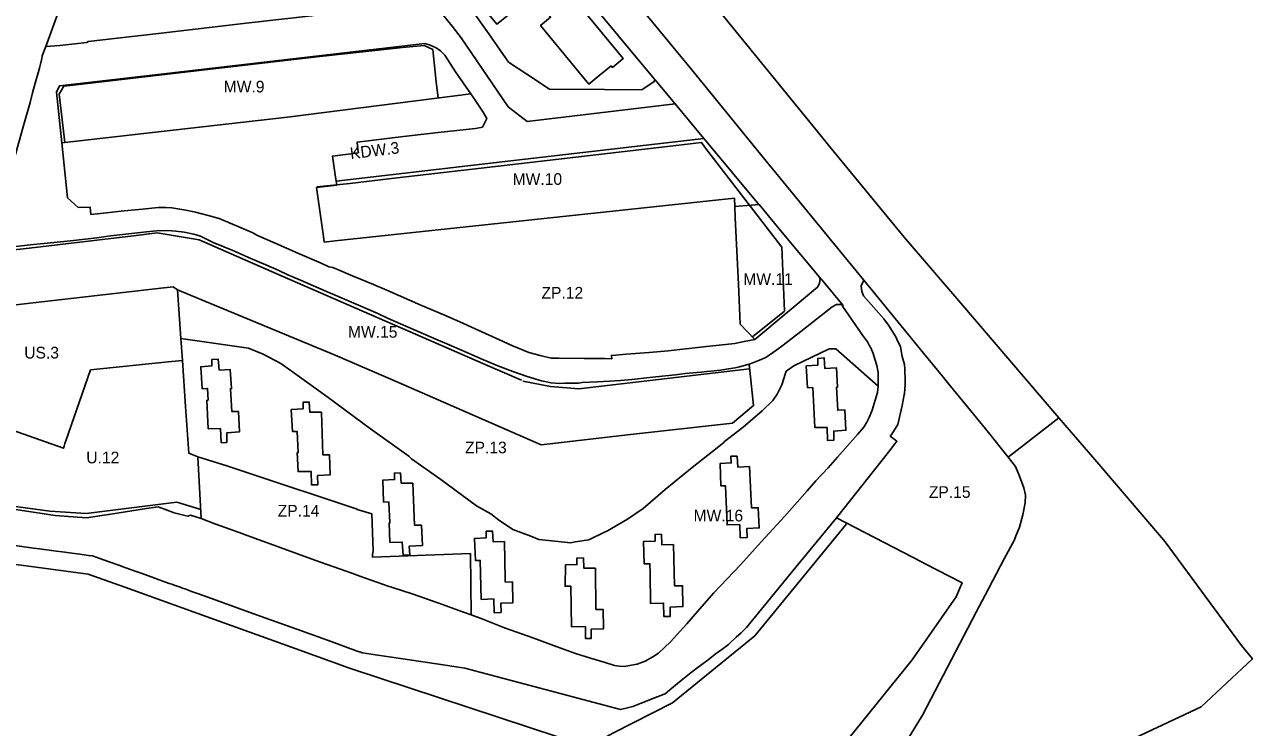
# Model space of a CAD drawing. Extents: x 7428689 to 7430424, y 5549101 to 5550539.
# Drawn here: x 7429899 to 7430424, y 5549654 to 5549955 of the extents above; entities that cross this region are included whole.
import ezdxf

# ---------------------------------------------------------------- set-up
doc = ezdxf.new("R2010")
doc.units = 0
for name, color, linetype in [('linie rozgraniczające', 7, 'Continuous'), ('nieprzekraczalne linie zabudowy', 7, 'Continuous'), ('obowiazujace linie zabudowy', 7, 'Continuous'), ('przeznaczenia terenów', 7, 'Continuous')]:
    doc.layers.add(name, color=color, linetype=linetype)

msp = doc.modelspace()

# ---------------------------------------------------------------- linework, layer by layer
at = {"layer": 'linie rozgraniczające'}
for points in [[(7429816.83, 5550334.12), (7429833.34, 5550323.51), (7429855.56, 5550306.27), (7429881.93, 5550290.04), (7429926.89, 5550263.18), (7429964.68, 5550236.86), (7430011.43, 5550186.87), (7430059.81, 5550126.71), (7430101.57, 5550076.38), (7430124.52, 5550048.84), (7430239.35, 5549907.74), (7430243.53, 5549902.67), (7430275.28, 5549864.05), (7430299.52, 5549835.73), (7430341.5, 5549786.7)], [(7430258.04, 5549845.58), (7430248.2, 5549857.63), (7430222.19, 5549889.25), (7430215.68, 5549897.16), (7430184.53, 5549935.61), (7430156.23, 5549969.99), (7430153.13, 5549973.76), (7430122.35, 5550011.53), (7430090.9, 5550049.78), (7430068.9, 5550076.43)], [(7430096.23, 5550017.94), (7430104.53, 5550007.9), (7430112.53, 5549999.04), (7430137.26, 5549969.22), (7430168.39, 5549931.68), (7430168.64, 5549931.38)], [(7430168.64, 5549931.38), (7430168.37, 5549930.61), (7430163.03, 5549927.09), (7430147.1, 5549927.18), (7430123.56, 5549927.32), (7430113.91, 5549933.66), (7430105.97, 5549938.87), (7430097.56, 5549950.93), (7430089.55, 5549962.42), (7430083.75, 5549970.74), (7430074.73, 5549983.7), (7430067.39, 5549994.23)], [(7429908.04, 5549945.59), (7429916.81, 5549969.68)], [(7430085.82, 5549949.33), (7430081.94, 5549954.22), (7430076.43, 5549961.08), (7430066.36, 5549963.92), (7430053.83, 5549962.51), (7430036.17, 5549960.52), (7430026.92, 5549959.51), (7430021.76, 5549958.62), (7429993.81, 5549955.51), (7429956.35, 5549951.19), (7429926.16, 5549947.7), (7429925.68, 5549947.31), (7429914.12, 5549946.03), (7429908.04, 5549945.59)], [(7429914.96, 5549904.32), (7429912.68, 5549925.96), (7429913.89, 5549928.71), (7429960.94, 5549934.15), (7430070.26, 5549946.8), (7430072.5, 5549946.14), (7430075.15, 5549944.97), (7430077, 5549943.65), (7430078.75, 5549941.8), (7430083.3, 5549934.76), (7430089.91, 5549925.26)], [(7430177.27, 5549921.04), (7430114.02, 5549913.44), (7430105.92, 5549919.76), (7430085.82, 5549949.33)], [(7429908.04, 5549945.59), (7429906.58, 5549941.5), (7429906.31, 5549940.37), (7429905.33, 5549936.24), (7429903.54, 5549929.81), (7429902.43, 5549925.68), (7429901.44, 5549921.63), (7429898.46, 5549911.23), (7429894.97, 5549898.89), (7429891.24, 5549885.87), (7429889.75, 5549880.65), (7429893.15, 5549880.55), (7429892.34, 5549877.29), (7429887.85, 5549859.16)], [(7430177.27, 5549921.04), (7430168.64, 5549931.38)], [(7430089.91, 5549925.26), (7430011.45, 5549915.27), (7429956.31, 5549909.01), (7429914.96, 5549904.32)], [(7430089.91, 5549925.26), (7430091.18, 5549923.44), (7430095.26, 5549917.51), (7430096.74, 5549914.71), (7430094.9, 5549911.04), (7430091.98, 5549910.54), (7430075.97, 5549908.75), (7430061.15, 5549907.03), (7430041.31, 5549904.65), (7430041.59, 5549901.54), (7430041.8, 5549900.07), (7430030.69, 5549898.67), (7430031.86, 5549890.61), (7430032.24, 5549887.95)], [(7430189.61, 5549906.24), (7430177.27, 5549921.04)], [(7430211.47, 5549820.24), (7430206.91, 5549819.33), (7430202.91, 5549818.53), (7430189.5, 5549817.02), (7430174.34, 5549815.35), (7430166.24, 5549814.68), (7430156.4, 5549813.89), (7430151.99, 5549813.53), (7430150.09, 5549813.41), (7430150.19, 5549811.98), (7430147.22, 5549812.01), (7430138.41, 5549812.09), (7430127.51, 5549812.27), (7430124.34, 5549812.27), (7430119.58, 5549813.34), (7430114.77, 5549814.61), (7430107.43, 5549817.59), (7430102.19, 5549820.05), (7430099.06, 5549821.48), (7430091.71, 5549824.81), (7430085.17, 5549827.71), (7430078.38, 5549830.69), (7430068.58, 5549834.93), (7430053.93, 5549841.36), (7430048.22, 5549843.67), (7430039.64, 5549847.28), (7430033.57, 5549849.86), (7430030.91, 5549850.97), (7430029.17, 5549851.33), (7430025.95, 5549852.87), (7430015.91, 5549857.2), (7430006.19, 5549861.45), (7429998.69, 5549864.66), (7429996.39, 5549866.03), (7429982.26, 5549872), (7429978.17, 5549873.11), (7429972.18, 5549874.66), (7429967.93, 5549875.57), (7429961.94, 5549876.49), (7429959.48, 5549876.73), (7429956.1, 5549876.69), (7429949.4, 5549875.97), (7429941.66, 5549875.3), (7429934, 5549874.38), (7429927.33, 5549873.75), (7429926.99, 5549876.86), (7429921.98, 5549876.65), (7429917.42, 5549880.87), (7429914.96, 5549904.32)], [(7430032.24, 5549887.95), (7430099.64, 5549895.78), (7430189.61, 5549906.24)], [(7430213.22, 5549877.92), (7430213.14, 5549878.02), (7430190.61, 5549905.04), (7430189.61, 5549906.24)], [(7430202.85, 5549877.11), (7430202.7, 5549880.65), (7430031.88, 5549862.4), (7430027.23, 5549861.91), (7430026.72, 5549865.46), (7430026.71, 5549865.47), (7430026.46, 5549867.28), (7430023.96, 5549885.17), (7430032.53, 5549886.26), (7430032.24, 5549887.95)], [(7430213.22, 5549877.92), (7430202.85, 5549877.11)], [(7430239.09, 5549846.91), (7430223.13, 5549866.05), (7430213.22, 5549877.92)], [(7430211.47, 5549820.24), (7430205.17, 5549826.7), (7430204.38, 5549843.82), (7430203.07, 5549872.23), (7430202.85, 5549877.11)], [(7429887.85, 5549859.16), (7429901.45, 5549860.72), (7429911.55, 5549861.69), (7429918.71, 5549862.38), (7429929.84, 5549863.74), (7429935.75, 5549864.53), (7429943.45, 5549865.41), (7429951.15, 5549866.2), (7429955.39, 5549866.68), (7429960.28, 5549866.87), (7429963.77, 5549866.59), (7429967.27, 5549866.07), (7429971.35, 5549865.2), (7429974.28, 5549864.35), (7429979.75, 5549861.75), (7429988.81, 5549857.94), (7429994.74, 5549855.28), (7430002.21, 5549852.08), (7430007.73, 5549849.69), (7430011.59, 5549847.91), (7430017.07, 5549845.63), (7430022.59, 5549843.17), (7430027.23, 5549841.2), (7430031.84, 5549839.21), (7430037.9, 5549836.59), (7430044.82, 5549833.6), (7430050.07, 5549831.3), (7430054.28, 5549829.35), (7430059.82, 5549826.94), (7430066.41, 5549824.04), (7430073.99, 5549820.8), (7430081.58, 5549817.5), (7430088.21, 5549814.6), (7430095.32, 5549811.53), (7430101.5, 5549808.99), (7430107.85, 5549806.51), (7430114.01, 5549804.35), (7430120.22, 5549802.55), (7430124.23, 5549801.61), (7430127.88, 5549801.42), (7430130.13, 5549801.52), (7430135.95, 5549801.57), (7430137.56, 5549801.78), (7430143.97, 5549802.1), (7430149.26, 5549802.33), (7430153.9, 5549802.69), (7430158.79, 5549803.13), (7430166.41, 5549803.89), (7430173.16, 5549804.68), (7430177.52, 5549805.14), (7430181.61, 5549805.63), (7430188.42, 5549806.26), (7430190.87, 5549806.49), (7430192.63, 5549806.65), (7430196.76, 5549807.15), (7430200.21, 5549807.58), (7430203.03, 5549808.09), (7430204.93, 5549808.47), (7430208.47, 5549809.5), (7430208.97, 5549809.68)], [(7430239.09, 5549846.91), (7430239.33, 5549845.93), (7430239.25, 5549845.1), (7430239.08, 5549844.32), (7430238.42, 5549842.71), (7430238.26, 5549842.57), (7430211.47, 5549820.24)], [(7430249.2, 5549834.78), (7430240.88, 5549844.76), (7430239.09, 5549846.91)], [(7429881.49, 5549833.5), (7429958.54, 5549842.32), (7429958.76, 5549842.35), (7429962.6, 5549842.78), (7429964.4, 5549841.52)], [(7429964.4, 5549841.52), (7429965.85, 5549820.63)], [(7430208.97, 5549809.68), (7430210.81, 5549791.9), (7430201.89, 5549784.46), (7430158.16, 5549779.51), (7430119.94, 5549775.19), (7430058.9, 5549801.77), (7430031.87, 5549813.54), (7429964.4, 5549841.52)], [(7430258.04, 5549845.58), (7430256.98, 5549843.23), (7430257.18, 5549840.73), (7430257.94, 5549838.91), (7430266.64, 5549829.1), (7430268.58, 5549826.4), (7430271.78, 5549821.3), (7430272.2, 5549820.36), (7430273.68, 5549817.02), (7430274.48, 5549812.98), (7430275.46, 5549809.46), (7430275.56, 5549807.49), (7430275.64, 5549805.71), (7430275.69, 5549804.29), (7430275.8, 5549801.16), (7430275.46, 5549796.89), (7430275.38, 5549796.54), (7430274.39, 5549791.9), (7430272.56, 5549783.86), (7430270.02, 5549779.69), (7430269.38, 5549778.88), (7430272.21, 5549776.64), (7430271.37, 5549775.51), (7430268.54, 5549771.99), (7430246.32, 5549743.93)], [(7430319.78, 5549769.81), (7430311.41, 5549780.44), (7430302.38, 5549791.45), (7430294.46, 5549801.11), (7430291.51, 5549804.71), (7430283.63, 5549814.32), (7430279.79, 5549819), (7430276.63, 5549822.86), (7430258.04, 5549845.58)], [(7430208.97, 5549809.68), (7430210.63, 5549810.27), (7430213.37, 5549811.3), (7430213.38, 5549811.3), (7430216.11, 5549812.55), (7430220.77, 5549815.83), (7430223.52, 5549817.74), (7430231.09, 5549823.61), (7430241.78, 5549831.97), (7430244.53, 5549834.14), (7430246.38, 5549835.2), (7430248.41, 5549835.14), (7430249.2, 5549834.78)], [(7430264.21, 5549800.27), (7430264.24, 5549800.51), (7430264.24, 5549804.01), (7430264.2, 5549806.07), (7430263.57, 5549809.01), (7430262.82, 5549811.82), (7430262.02, 5549814.28), (7430260.99, 5549816.63), (7430260.31, 5549817.78), (7430259.56, 5549819.17), (7430257.5, 5549822.1), (7430254.36, 5549826.67), (7430248.89, 5549834.52), (7430249.2, 5549834.78)], [(7429966.5, 5549811.25), (7429965.85, 5549820.63)], [(7429965.85, 5549820.63), (7429994.82, 5549816.43), (7430001.1, 5549813.98), (7430008.63, 5549809.93), (7430013.09, 5549806.85), (7430028.37, 5549795.77), (7430046.99, 5549781.94), (7430063.35, 5549770.24), (7430064.48, 5549769.19), (7430077.06, 5549760.25), (7430092.39, 5549749.02), (7430098.43, 5549745.65), (7430101.78, 5549743.1), (7430107.95, 5549738.97), (7430115.55, 5549736.02), (7430118.96, 5549734.65), (7430132.66, 5549733.27), (7430134.56, 5549733.6), (7430140.46, 5549734.45), (7430147.09, 5549737.73), (7430148.39, 5549738.4), (7430148.45, 5549738.38), (7430156.95, 5549743.31), (7430163.6, 5549747.86), (7430173.04, 5549755.99), (7430184.58, 5549765.43), (7430197.96, 5549776.06), (7430198.48, 5549776.57), (7430206.42, 5549782.66), (7430214.61, 5549789.67), (7430219.07, 5549794.13), (7430220.91, 5549796.82), (7430223, 5549800.82), (7430224.58, 5549805.8), (7430224.84, 5549806.65), (7430228.12, 5549808.95), (7430243.26, 5549816.22), (7430246.02, 5549816.22), (7430264.21, 5549800.27)], [(7429871.39, 5549789.01), (7429888.46, 5549783.29), (7429915.65, 5549773.69), (7429915.92, 5549774.62), (7429916.18, 5549775.67), (7429916.58, 5549776.86), (7429927.23, 5549807.18), (7429960.39, 5549810.65), (7429966.5, 5549811.25)], [(7429973.11, 5549770.05), (7429969.26, 5549771.62), (7429967.87, 5549791.56), (7429966.5, 5549811.25)], [(7430264.21, 5549800.27), (7430263.85, 5549797.5), (7430262.93, 5549794.28), (7430261.58, 5549789.92), (7430260.31, 5549786.82), (7430259.36, 5549784.88), (7430258.09, 5549782.73), (7430255.31, 5549779.52), (7430251.07, 5549774.76), (7430246.74, 5549769.87), (7430242.77, 5549765.35), (7430237.52, 5549759.67), (7430233.8, 5549755.49), (7430224.17, 5549744.54), (7430214.33, 5549733.8), (7430205.33, 5549723.8), (7430193.95, 5549711.76), (7430187.77, 5549704.81), (7430182.27, 5549698.62), (7430175.29, 5549690.84), (7430170.21, 5549686.03), (7430167.72, 5549684.49), (7430164.49, 5549682.64), (7430161.1, 5549681.26), (7430157.03, 5549680.55), (7430155.71, 5549680.36), (7430153.32, 5549680.42), (7430151.37, 5549680.73), (7430147.35, 5549681.95), (7430141.05, 5549683.8), (7430134.7, 5549685.81), (7430126.87, 5549688.67), (7430116.44, 5549692.54), (7430104.35, 5549696.84), (7430095.06, 5549700.48), (7430090.02, 5549702.34)], [(7430341.5, 5549786.7), (7430319.78, 5549769.81)], [(7430341.5, 5549786.7), (7430357.67, 5549767.81), (7430385.38, 5549735.44), (7430386.97, 5549733.58), (7430419.63, 5549689.34), (7430424.31, 5549683.55), (7430402.43, 5549663.1), (7430345.97, 5549636.49)], [(7429973.11, 5549770.05), (7429974.57, 5549743.68)], [(7430090.02, 5549702.34), (7430089.78, 5549728.62), (7430047.91, 5549727.05), (7430047.82, 5549727.57), (7430047.91, 5549728.19), (7430048.08, 5549729.76), (7430047.56, 5549745.67), (7430041.34, 5549747.48), (7430041.33, 5549747.63), (7429994.1, 5549763.35), (7429985.59, 5549766.18), (7429973.11, 5549770.05)], [(7430228.77, 5549605.53), (7430233.54, 5549609.48), (7430238.8, 5549613.84), (7430249.41, 5549622.63), (7430262.18, 5549633.21), (7430267.94, 5549638.53), (7430271.74, 5549642.65), (7430274.9, 5549646.31), (7430278.07, 5549651.09), (7430283.22, 5549659.41), (7430306.17, 5549703.55), (7430310.02, 5549710.88), (7430318.16, 5549726.37), (7430322.45, 5549734.55), (7430322.97, 5549735.78), (7430324.7, 5549739.87), (7430326.07, 5549745.24), (7430327.07, 5549750.27), (7430327.17, 5549753.54), (7430326.55, 5549756.79), (7430324.71, 5549761.7), (7430322.93, 5549765.87), (7430319.78, 5549769.81)], [(7429974.57, 5549743.68), (7429969.96, 5549745.05), (7429968.9, 5549744.66), (7429967.51, 5549744.92), (7429963.01, 5549746.11), (7429960.03, 5549747.24), (7429956.2, 5549748.63), (7429951.17, 5549747.9), (7429935.89, 5549745.52), (7429925.52, 5549743.92), (7429912.08, 5549744.96), (7429871.59, 5549750.98), (7429863.62, 5549752.17)], [(7429894.89, 5549732.03), (7429902.84, 5549730.96), (7429905.36, 5549730.62), (7429911.49, 5549729.81), (7429916.16, 5549729.18), (7429919.26, 5549728.77), (7429922.67, 5549728.31), (7429926.32, 5549727.82), (7429928.12, 5549727.58), (7429931.23, 5549726.47), (7429935.12, 5549725.08), (7429939.3, 5549723.59), (7429941.93, 5549722.64), (7429944.7, 5549721.66), (7429946.29, 5549721.09), (7429948.81, 5549720.19), (7429951.63, 5549719.18), (7429953.52, 5549718.5), (7429956.52, 5549717.43), (7429958.12, 5549716.86), (7429960.9, 5549715.87), (7429962.01, 5549715.47), (7429962.98, 5549715.12), (7429964.32, 5549714.65), (7429965.66, 5549714.17), (7429966.13, 5549714), (7429968.02, 5549713.33), (7429970.17, 5549712.56), (7429970.48, 5549712.45), (7429973.37, 5549711.41), (7429980.97, 5549708.67), (7429989.9, 5549705.46), (7430002.18, 5549701.03), (7430017.48, 5549695.51), (7430030.14, 5549690.95), (7430041.33, 5549686.91), (7430043.64, 5549686.08), (7430049.06, 5549685.28), (7430060.86, 5549683.53), (7430078.12, 5549680.97), (7430087.31, 5549679.61), (7430153.96, 5549661.92), (7430156.95, 5549662.67), (7430159.25, 5549663.24), (7430162.8, 5549664.61), (7430168.2, 5549666.7), (7430172.65, 5549668.43), (7430173.09, 5549668.6), (7430175.95, 5549670.98), (7430179.87, 5549674.24), (7430182.77, 5549676.65), (7430183.41, 5549677.18), (7430183.71, 5549677.41), (7430184.77, 5549678.2), (7430186.59, 5549679.56), (7430188.71, 5549681.15), (7430191.39, 5549683.16), (7430194.52, 5549685.51), (7430197.35, 5549687.63), (7430199.58, 5549689.3), (7430200.14, 5549689.72), (7430200.45, 5549689.95), (7430203.47, 5549692.83), (7430205.51, 5549694.77), (7430207.86, 5549697.01), (7430228.94, 5549722.73), (7430228.96, 5549722.75), (7430246.32, 5549743.93)], [(7429974.57, 5549743.68), (7429980.41, 5549741.35), (7429989.2, 5549738.17), (7429995.75, 5549735.79), (7430000.89, 5549733.97), (7430023.24, 5549725.82), (7430038.96, 5549720.22), (7430042.44, 5549719.01), (7430054.51, 5549714.67), (7430056.43, 5549714.07), (7430064.85, 5549711.44), (7430070.54, 5549709.41), (7430077.83, 5549706.79), (7430084.77, 5549704.28), (7430090.02, 5549702.34)], [(7430246.32, 5549743.93), (7430282.98, 5549724.94), (7430284.25, 5549724.28), (7430300.17, 5549716.04), (7430299.19, 5549713.83), (7430297.51, 5549710.06), (7430278.78, 5549683.08)], [(7430278.78, 5549683.08), (7430236.19, 5549630.56), (7430233.05, 5549626.69), (7430232.85, 5549626.44), (7430223.88, 5549615.37), (7430222.27, 5549614.15), (7430228.77, 5549605.53)]]:
    msp.add_lwpolyline(points, dxfattribs=at)
at = {"layer": 'nieprzekraczalne linie zabudowy'}
for points in [[(7430075.91, 5549923.48), (7430075.12, 5549930.49), (7430073.92, 5549941.4), (7430073.61, 5549944.26), (7430069.89, 5549946.05), (7430060.75, 5549945.15), (7430024.03, 5549941.08), (7429976.15, 5549935.53), (7429919.83, 5549929.06), (7429915.81, 5549928.55), (7429913.78, 5549925.22), (7429916.19, 5549904.46)], [(7430210.39, 5549821.35), (7430224.1, 5549832.33), (7430222.91, 5549859.76), (7430189.89, 5549902.69), (7430188.61, 5549904.55), (7430178.88, 5549903.36), (7430126.26, 5549897.26), (7430094.27, 5549893.5), (7430058.35, 5549889.37), (7430038.11, 5549886.99), (7430023.99, 5549885.45)], [(7430111.57, 5549802.73), (7430095, 5549809.98), (7430066.31, 5549822.5), (7430009.14, 5549847.36), (7429973.71, 5549862.79), (7429955.71, 5549865.8), (7429945.64, 5549864.49), (7429898.6, 5549859.06), (7429886.83, 5549857.85)], [(7430209.15, 5549807.66), (7430136.17, 5549799.07), (7430123.98, 5549800.05), (7430112.11, 5549802.34)], [(7429863.89, 5549753.68), (7429892, 5549749.19), (7429909.82, 5549746.79), (7429925.29, 5549745.77), (7429964.11, 5549750.56), (7429974.36, 5549747.45)], [(7430250.82, 5549741.6), (7430250.19, 5549740.76), (7430211.41, 5549693.45), (7430176.25, 5549664.73), (7430150.63, 5549651.76), (7430140.11, 5549645.96), (7430038.01, 5549679.61), (7430014.8, 5549687.97), (7429975.18, 5549702.22), (7429941.88, 5549714.17), (7429926.22, 5549719.76), (7429897.47, 5549723.61), (7429891.43, 5549724.32), (7429865.45, 5549636.95), (7429840.64, 5549623.35), (7429816.77, 5549526.64), (7429810.79, 5549500.32)]]:
    msp.add_lwpolyline(points, dxfattribs=at)
at = {"layer": 'obowiazujace linie zabudowy'}
for points in [[(7430100.69, 5549982.89), (7430101.39, 5549983.47), (7430084.39, 5550004.03), (7430079.67, 5550000.13), (7430080.43, 5549999.23), (7430075.15, 5549994.87), (7430071.11, 5549991.43), (7430101.06, 5549955.06), (7430105.13, 5549958.43), (7430116.3, 5549967.6), (7430124.01, 5549958.08), (7430119.73, 5549954.55), (7430140.42, 5549929.45), (7430144.69, 5549932.97), (7430149.92, 5549937.27), (7430150.46, 5549936.61), (7430155.07, 5549940.41), (7430117, 5549986.63), (7430113.09, 5549983.47), (7430115.92, 5549979.93), (7430109.04, 5549974.18), (7430108.31, 5549973.63), (7430100.69, 5549982.89)], [(7429982.18, 5549807.13), (7429981.83, 5549811.72), (7429979.04, 5549811.59), (7429979.09, 5549808.93), (7429974.37, 5549808.54), (7429974.98, 5549799.16), (7429977.28, 5549799.26), (7429977.54, 5549794.26), (7429976.95, 5549794.11), (7429977.59, 5549782), (7429982.75, 5549782.12), (7429983.14, 5549776.01), (7429985.59, 5549776.14), (7429985.55, 5549780.32), (7429990.99, 5549780.71), (7429990.58, 5549789.37), (7429987.68, 5549789.34), (7429987.09, 5549799.13), (7429987.55, 5549799.2), (7429987, 5549807.36), (7429982.18, 5549807.13)], [(7430233.43, 5549808.87), (7430233.98, 5549799.59), (7430236.23, 5549799.65), (7430237.14, 5549782.51), (7430242.3, 5549782.57), (7430242.53, 5549776.97), (7430245.25, 5549777.14), (7430245.15, 5549781.02), (7430250.42, 5549781.37), (7430249.94, 5549790.08), (7430246.9, 5549789.96), (7430246.4, 5549799.76), (7430246.8, 5549799.84), (7430246.38, 5549808.04), (7430241.34, 5549807.8), (7430241.15, 5549812.29), (7430238.36, 5549812.14), (7430238.4, 5549809.28), (7430233.43, 5549808.87)], [(7430025.99, 5549789.04), (7430021.04, 5549789.05), (7430020.82, 5549793.44), (7430018.18, 5549793.35), (7430018.18, 5549790.55), (7430013.07, 5549790.19), (7430013.56, 5549780.88), (7430015.67, 5549780.81), (7430016.1, 5549771.84), (7430015.65, 5549771.81), (7430016, 5549763.69), (7430021.55, 5549763.74), (7430021.8, 5549757.98), (7430024.45, 5549758.08), (7430024.37, 5549761.95), (7430029.72, 5549762.28), (7430029.38, 5549770.92), (7430026.61, 5549770.82), (7430025.99, 5549789.04)], [(7430203.93, 5549770.33), (7430201.21, 5549770.25), (7430201.33, 5549767.4), (7430196.55, 5549767.09), (7430196.93, 5549757.56), (7430198.86, 5549757.66), (7430199.56, 5549740.84), (7430204.99, 5549740.99), (7430205.16, 5549735.32), (7430208.08, 5549735.43), (7430208.02, 5549739.34), (7430213.33, 5549739.59), (7430212.88, 5549748.25), (7430210.06, 5549748.13), (7430209.18, 5549765.85), (7430204.17, 5549765.64), (7430203.93, 5549770.33)], [(7430059.86, 5549763.16), (7430057.2, 5549763.04), (7430057.27, 5549760.24), (7430052.29, 5549760.02), (7430052.55, 5549750.73), (7430054.89, 5549750.67), (7430055.33, 5549741.74), (7430054.93, 5549741.7), (7430055.32, 5549733.37), (7430060.61, 5549733.52), (7430060.91, 5549727.95), (7430063.77, 5549728.06), (7430063.6, 5549731.83), (7430069.21, 5549732.07), (7430068.83, 5549740.71), (7430065.87, 5549740.72), (7430065.04, 5549758.73), (7430060.12, 5549758.7), (7430059.86, 5549763.16)], [(7430104.29, 5549733.79), (7430099.53, 5549733.58), (7430099.24, 5549738.26), (7430096.42, 5549738.17), (7430096.53, 5549735.38), (7430091.42, 5549735.09), (7430091.85, 5549725.69), (7430093.93, 5549725.71), (7430094.36, 5549708.98), (7430099.7, 5549709.21), (7430099.91, 5549703.25), (7430102.84, 5549703.46), (7430102.76, 5549707.44), (7430107.94, 5549707.55), (7430107.78, 5549716.47), (7430104.65, 5549716.41), (7430104.57, 5549717.7), (7430104.29, 5549733.79)], [(7430176.66, 5549732.44), (7430171.64, 5549732.39), (7430171.44, 5549736.86), (7430168.73, 5549736.78), (7430168.76, 5549733.89), (7430163.73, 5549733.76), (7430164.13, 5549724.2), (7430166.56, 5549724.25), (7430166.59, 5549720.22), (7430166.82, 5549707.3), (7430172.35, 5549707.41), (7430172.5, 5549701.66), (7430175.25, 5549701.71), (7430175.26, 5549705.74), (7430180.67, 5549705.93), (7430180.53, 5549714.83), (7430177.11, 5549714.86), (7430176.96, 5549720.64), (7430176.66, 5549732.44)], [(7430143.29, 5549722.41), (7430138.26, 5549722.39), (7430138.05, 5549726.78), (7430135.3, 5549726.68), (7430135.27, 5549723.92), (7430130.36, 5549723.75), (7430130.24, 5549714.62), (7430132.68, 5549714.63), (7430133.04, 5549697.33), (7430138.95, 5549697.36), (7430138.99, 5549692.21), (7430141.38, 5549692.25), (7430141.43, 5549696.23), (7430146.62, 5549696.41), (7430146.53, 5549704.71), (7430143.4, 5549704.71), (7430143.29, 5549722.41)]]:
    msp.add_lwpolyline(points, dxfattribs=at)

# ---------------------------------------------------------------- texts
at = {"layer": 'przeznaczenia terenów'}
for s, p in [('MW.9', (7429984.18, 5549925.9)), ('MW.10', (7430107.79, 5549886.36)), ('MW.11', (7430206.48, 5549843.54)), ('ZP.12', (7430120.13, 5549837.7)), ('MW.15', (7430037.34, 5549820.97)), ('US.3', (7429898.85, 5549812.07)), ('ZP.13', (7430087.43, 5549771.49)), ('U.12', (7429925.4, 5549767.21)), ('ZP.15', (7430285.88, 5549752.44)), ('ZP.14', (7430007.3, 5549744.45)), ('MW.16', (7430185.21, 5549742.36))]:
    msp.add_text(s, height=5, dxfattribs=at).set_placement(p)
msp.add_text('KDW.3', height=5, rotation=7.0802, dxfattribs=at).set_placement((7430038.55, 5549897.29))

doc.saveas('drawing.dxf')
